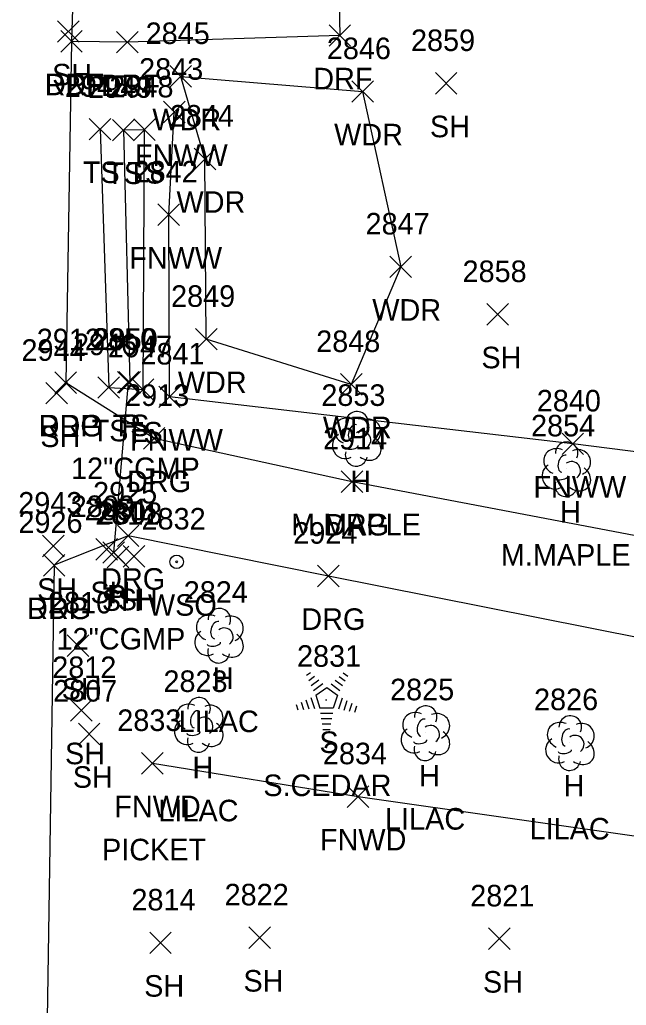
# Model space of a CAD drawing. Extents: x 1609623 to 1616187, y 756677 to 762826.
# Drawn here: x 1610616 to 1610672.3, y 761993.3 to 762084.8 of the extents above; entities that cross this region are included whole.
import ezdxf

# ---------------------------------------------------------------- set-up
doc = ezdxf.new("R2010")
doc.units = 0
for name, color, linetype in [('D_A', 7, 'Continuous'), ('D_C', 7, 'Continuous'), ('D_I', 7, 'Continuous'), ('D_TIC', 7, 'Continuous'), ('DCP', 7, 'Continuous'), ('L_A', 7, 'Continuous'), ('L_C', 7, 'Continuous'), ('L_I', 7, 'Continuous'), ('L_TIC', 7, 'Continuous'), ('LAWA', 7, 'Continuous'), ('LELB', 7, 'Continuous'), ('LFNC', 7, 'Continuous'), ('LTC', 7, 'Continuous'), ('LTD', 7, 'Continuous'), ('P_A', 7, 'Continuous'), ('P_I', 7, 'Continuous'), ('P_TIC', 7, 'Continuous'), ('PET', 7, 'Continuous'), ('R_A', 7, 'Continuous'), ('R_I', 7, 'Continuous'), ('R_TIC', 7, 'Continuous'), ('RDF', 7, 'Continuous'), ('RDG', 7, 'Continuous'), ('U_A', 7, 'Continuous'), ('U_I', 7, 'Continuous'), ('UWV', 7, 'Continuous')]:
    doc.layers.add(name, color=color, linetype=linetype)

msp = doc.modelspace()

# ---------------------------------------------------------------- linework, layer by layer
at = {"layer": 'D_TIC'}
for points in [[(1610625.028, 762050.167), (1610627.028, 762052.167)], [(1610627.028, 762050.167), (1610625.028, 762052.167)], [(1610623.685, 762034.355), (1610625.685, 762036.355)], [(1610625.685, 762034.355), (1610623.685, 762036.355)]]:
    msp.add_lwpolyline(points, dxfattribs=at)
at = {"layer": 'DCP'}
msp.add_lwpolyline([(1610626.028, 762051.167), (1610624.685, 762035.355)], dxfattribs=at)
at = {"layer": 'L_TIC'}
for points in [[(1610619.487, 762082.696), (1610621.487, 762084.696)], [(1610621.487, 762082.696), (1610619.487, 762084.696)], [(1610629.913, 762078.538), (1610631.913, 762080.538)], [(1610631.913, 762078.538), (1610629.913, 762080.538)], [(1610654.549, 762077.888), (1610656.549, 762079.888)], [(1610656.549, 762077.888), (1610654.549, 762079.888)], [(1610646.786, 762077.134), (1610648.786, 762079.134)], [(1610648.786, 762077.134), (1610646.786, 762079.134)], [(1610629.31, 762075.224), (1610631.31, 762077.224)], [(1610631.31, 762075.224), (1610629.31, 762077.224)], [(1610622.417, 762073.638), (1610624.417, 762075.638)], [(1610624.417, 762073.638), (1610622.417, 762075.638)], [(1610624.586, 762073.545), (1610626.586, 762075.545)], [(1610626.586, 762073.545), (1610624.586, 762075.545)], [(1610626.549, 762073.587), (1610628.549, 762075.587)], [(1610628.549, 762073.587), (1610626.549, 762075.587)], [(1610632.154, 762070.879), (1610634.154, 762072.879)], [(1610634.154, 762070.879), (1610632.154, 762072.879)], [(1610628.792, 762065.698), (1610630.792, 762067.698)], [(1610630.792, 762065.698), (1610628.792, 762067.698)], [(1610650.324, 762060.865), (1610652.324, 762062.865)], [(1610652.324, 762060.865), (1610650.324, 762062.865)], [(1610659.325, 762056.449), (1610661.325, 762058.449)], [(1610661.325, 762056.449), (1610659.325, 762058.449)], [(1610632.28, 762054.151), (1610634.28, 762056.151)], [(1610634.28, 762054.151), (1610632.28, 762056.151)], [(1610625.173, 762050.15), (1610627.173, 762052.15)], [(1610627.173, 762050.15), (1610625.173, 762052.15)], [(1610623.227, 762049.668), (1610625.227, 762051.668)], [(1610625.227, 762049.668), (1610623.227, 762051.668)], [(1610626.411, 762049.471), (1610628.411, 762051.471)], [(1610628.411, 762049.471), (1610626.411, 762051.471)], [(1610645.741, 762049.958), (1610647.741, 762051.958)], [(1610647.741, 762049.958), (1610645.741, 762051.958)], [(1610618.39, 762049.14), (1610620.39, 762051.14)], [(1610620.39, 762049.14), (1610618.39, 762051.14)], [(1610628.863, 762048.802), (1610630.863, 762050.802)], [(1610630.863, 762048.802), (1610628.863, 762050.802)], [(1610666.301, 762044.445), (1610668.301, 762046.445)], [(1610668.301, 762044.445), (1610666.301, 762046.445)], [(1610618.09, 762034.964), (1610620.09, 762036.964)], [(1610620.09, 762034.964), (1610618.09, 762036.964)], [(1610623.041, 762034.648), (1610625.041, 762036.648)], [(1610625.041, 762034.648), (1610623.041, 762036.648)], [(1610624.097, 762033.94), (1610626.097, 762035.94)], [(1610626.097, 762033.94), (1610624.097, 762035.94)], [(1610625.576, 762033.997), (1610627.576, 762035.997)], [(1610627.576, 762033.997), (1610625.576, 762035.997)], [(1610620.371, 762025.706), (1610622.371, 762027.706)], [(1610622.371, 762025.706), (1610620.371, 762027.706)], [(1610620.678, 762019.708), (1610622.678, 762021.708)], [(1610622.678, 762019.708), (1610620.678, 762021.708)], [(1610621.406, 762017.523), (1610623.406, 762019.523)], [(1610623.406, 762017.523), (1610621.406, 762019.523)], [(1610627.279, 762014.794), (1610629.279, 762016.794)], [(1610629.279, 762014.794), (1610627.279, 762016.794)], [(1610646.364, 762011.709), (1610648.364, 762013.709)], [(1610648.364, 762011.709), (1610646.364, 762013.709)], [(1610628.028, 761998.14), (1610630.028, 762000.14)], [(1610630.028, 761998.14), (1610628.028, 762000.14)], [(1610637.242, 761998.612), (1610639.242, 762000.612)], [(1610639.242, 761998.612), (1610637.242, 762000.612)], [(1610659.471, 761998.517), (1610661.471, 762000.517)], [(1610661.471, 761998.517), (1610659.471, 762000.517)]]:
    msp.add_lwpolyline(points, dxfattribs=at)
at = {"layer": 'LAWA'}
for points in [[(1610633.154, 762071.879), (1610630.913, 762079.538), (1610647.786, 762078.134), (1610651.324, 762061.865), (1610646.741, 762050.958), (1610633.28, 762055.151)], [(1610633.28, 762055.151), (1610633.154, 762071.879)]]:
    msp.add_lwpolyline(points, dxfattribs=at)
at = {"layer": 'LELB'}
msp.add_lwpolyline([(1610623.417, 762074.638), (1610624.227, 762050.668), (1610627.411, 762050.471), (1610627.549, 762074.587), (1610625.586, 762074.545), (1610626.173, 762051.15)], dxfattribs=at)
at = {"layer": 'LFNC'}
for points in [[(1610758.962, 762033.074), (1610692.81, 762042.187), (1610667.301, 762045.445), (1610629.863, 762049.802), (1610629.792, 762066.698), (1610630.31, 762076.224)], [(1610628.279, 762015.794), (1610647.364, 762012.709), (1610689.696, 762006.674)]]:
    msp.add_lwpolyline(points, dxfattribs=at)
at = {"layer": 'LTC'}
for p, q in [((1610642.59, 762023.96), (1610642.945, 762024.217)), ((1610642.8, 762023.494), (1610643.329, 762023.878)), ((1610645.617, 762023.852), (1610646.167, 762023.453)), ((1610645.988, 762024.2), (1610646.408, 762023.896)), ((1610643.009, 762023.028), (1610643.713, 762023.54)), ((1610643.219, 762022.563), (1610644.097, 762023.201)), ((1610643.443, 762022.108), (1610644.455, 762022.842)), ((1610644.455, 762022.842), (1610645.452, 762022.117)), ((1610644.875, 762023.155), (1610645.685, 762022.566)), ((1610645.246, 762023.503), (1610645.925, 762023.01)), ((1610643.443, 762022.108), (1610643.83, 762020.914)), ((1610645.452, 762022.117), (1610645.061, 762020.914)), ((1610641.623, 762021.239), (1610641.775, 762020.771)), ((1610642.078, 762021.456), (1610642.29, 762020.804)), ((1610642.533, 762021.672), (1610642.805, 762020.837)), ((1610642.989, 762021.888), (1610643.32, 762020.869)), ((1610645.89, 762021.846), (1610645.552, 762020.807)), ((1610646.334, 762021.596), (1610646.047, 762020.711)), ((1610646.779, 762021.346), (1610646.542, 762020.616)), ((1610647.223, 762021.096), (1610647.036, 762020.521)), ((1610645.061, 762020.914), (1610643.83, 762020.914)), ((1610645.023, 762020.414), (1610643.878, 762020.414)), ((1610644.939, 762019.914), (1610643.95, 762019.914)), ((1610644.855, 762019.414), (1610644.023, 762019.414)), ((1610644.771, 762018.914), (1610644.096, 762018.914))]:
    msp.add_line(p, q, dxfattribs=at)
at = {"layer": 'LTD'}
for p, q in [((1610647.22, 762045.958), (1610647.22, 762045.958)), ((1610647.22, 762045.958), (1610647.22, 762045.958)), ((1610666.683, 762043.131), (1610666.683, 762043.131)), ((1610666.683, 762043.131), (1610666.683, 762043.131)), ((1610634.446, 762027.69), (1610634.446, 762027.69)), ((1610634.446, 762027.69), (1610634.446, 762027.69)), ((1610632.564, 762019.413), (1610632.564, 762019.413)), ((1610632.564, 762019.413), (1610632.564, 762019.413)), ((1610653.598, 762018.644), (1610653.598, 762018.644)), ((1610653.598, 762018.644), (1610653.598, 762018.644)), ((1610667.016, 762017.726), (1610667.016, 762017.726)), ((1610667.016, 762017.726), (1610667.016, 762017.726))]:
    msp.add_line(p, q, dxfattribs=at)
for centre in [(1610647.267, 762047.392), (1610666.729, 762044.565), (1610634.493, 762029.123), (1610632.611, 762020.847), (1610653.645, 762020.078), (1610667.062, 762019.16)]:
    msp.add_arc(centre, 1.047, 335.52715, 180.95627, dxfattribs=at)
for centre, major_axis, ratio, start_param, end_param in [((1610646.428, 762046.624), (1.21, -0.512), 0.895232, 1.570796, 4.712389), ((1610648.262, 762046.541), (-1.141, -0.483), 0.949671, 1.570796, 4.712389), ((1610647.012, 762046.416), (-0.208, -0.792), 0.645439, 3.141593, 6.283185), ((1610647.72, 762045.791), (-0.5, 0.667), 0.989748, 3.141593, 6.283185), ((1610646.137, 762045.249), (0.584, -1.042), 0.959034, 3.141593, 6.283185), ((1610648.22, 762045.125), (-1.09, 0.792), 0.841452, 1.570796, 4.712389), ((1610646.762, 762045.208), (-0.625, -0.083), 0.423636, 0, 3.141593), ((1610665.891, 762043.797), (1.21, -0.512), 0.895232, 1.570796, 4.712389), ((1610667.724, 762043.714), (-1.141, -0.483), 0.949671, 1.570796, 4.712389), ((1610647.22, 762044.458), (0.265, 1.061), 0.942809, 1.570796, 4.712389), ((1610666.474, 762043.589), (-0.208, -0.792), 0.645439, 3.141593, 6.283185), ((1610667.183, 762042.964), (-0.5, 0.667), 0.989748, 3.141593, 6.283185), ((1610665.599, 762042.422), (0.584, -1.042), 0.959034, 3.141593, 6.283185), ((1610667.683, 762042.298), (-1.09, 0.792), 0.841452, 1.570796, 4.712389), ((1610666.224, 762042.381), (-0.625, -0.083), 0.423636, 0, 3.141593), ((1610666.683, 762041.631), (0.265, 1.061), 0.942809, 1.570796, 4.712389), ((1610633.654, 762028.356), (1.21, -0.512), 0.895232, 1.570796, 4.712389), ((1610635.488, 762028.273), (-1.141, -0.483), 0.949671, 1.570796, 4.712389), ((1610634.238, 762028.148), (-0.208, -0.792), 0.645439, 3.141593, 6.283185), ((1610634.946, 762027.523), (-0.5, 0.667), 0.989748, 3.141593, 6.283185), ((1610633.363, 762026.981), (0.584, -1.042), 0.959034, 3.141593, 6.283185), ((1610635.446, 762026.856), (-1.09, 0.792), 0.841452, 1.570796, 4.712389), ((1610633.988, 762026.939), (-0.625, -0.083), 0.423636, 0, 3.141593), ((1610634.446, 762026.19), (0.265, 1.061), 0.942809, 1.570796, 4.712389), ((1610631.773, 762020.079), (1.21, -0.512), 0.895232, 1.570796, 4.712389), ((1610633.606, 762019.996), (-1.141, -0.483), 0.949671, 1.570796, 4.712389), ((1610632.356, 762019.871), (-0.208, -0.792), 0.645439, 3.141593, 6.283185), ((1610633.065, 762019.246), (-0.5, 0.667), 0.989748, 3.141593, 6.283185), ((1610652.806, 762019.31), (1.21, -0.512), 0.895232, 1.570796, 4.712389), ((1610654.64, 762019.227), (-1.141, -0.483), 0.949671, 1.570796, 4.712389), ((1610631.481, 762018.704), (0.584, -1.042), 0.959034, 3.141593, 6.283185), ((1610633.565, 762018.579), (-1.09, 0.792), 0.841452, 1.570796, 4.712389), ((1610653.39, 762019.102), (-0.208, -0.792), 0.645439, 3.141593, 6.283185), ((1610654.098, 762018.477), (-0.5, 0.667), 0.989748, 3.141593, 6.283185), ((1610666.224, 762018.392), (1.21, -0.512), 0.895232, 1.570796, 4.712389), ((1610668.057, 762018.309), (-1.141, -0.483), 0.949671, 1.570796, 4.712389), ((1610632.106, 762018.663), (-0.625, -0.083), 0.423636, 0, 3.141593), ((1610652.515, 762017.935), (0.584, -1.042), 0.959034, 3.141593, 6.283185), ((1610654.598, 762017.811), (-1.09, 0.792), 0.841452, 1.570796, 4.712389), ((1610666.807, 762018.184), (-0.208, -0.792), 0.645439, 3.141593, 6.283185), ((1610667.516, 762017.559), (-0.5, 0.667), 0.989748, 3.141593, 6.283185), ((1610632.565, 762017.913), (0.265, 1.061), 0.942809, 1.570796, 4.712389), ((1610653.599, 762017.144), (0.265, 1.061), 0.942809, 1.570796, 4.712389), ((1610653.14, 762017.894), (-0.625, -0.083), 0.423636, 0, 3.141593), ((1610665.932, 762017.017), (0.584, -1.042), 0.959034, 3.141593, 6.283185), ((1610668.016, 762016.893), (-1.09, 0.792), 0.841452, 1.570796, 4.712389), ((1610667.016, 762016.226), (0.265, 1.061), 0.942809, 1.570796, 4.712389), ((1610666.557, 762016.976), (-0.625, -0.083), 0.423636, 0, 3.141593)]:
    msp.add_ellipse(centre, major_axis=major_axis, ratio=ratio, start_param=start_param, end_param=end_param, dxfattribs=at)
at = {"layer": 'P_TIC'}
for points in [[(1610619.776, 762081.781), (1610621.776, 762083.781)], [(1610621.776, 762081.781), (1610619.776, 762083.781)], [(1610619.24, 762050.122), (1610621.24, 762052.122)], [(1610621.24, 762050.122), (1610619.24, 762052.122)], [(1610618.159, 762033.171), (1610620.159, 762035.171)], [(1610620.159, 762033.171), (1610618.159, 762035.171)]]:
    msp.add_lwpolyline(points, dxfattribs=at)
at = {"layer": 'PET'}
for points in [[(1610622.044, 762167.749), (1610622.434, 762137.471), (1610620.776, 762082.781), (1610620.24, 762051.122)], [(1610619.159, 762034.171), (1610618.457, 761988.073), (1610618.105, 761954.066), (1610618.601, 761923.518), (1610618.231, 761918.549), (1610617.677, 761897.504)]]:
    msp.add_lwpolyline(points, dxfattribs=at)
at = {"layer": 'R_TIC'}
for points in [[(1610644.675, 762082.332), (1610646.675, 762084.332)], [(1610646.675, 762082.332), (1610644.675, 762084.332)], [(1610619.776, 762081.781), (1610621.776, 762083.781)], [(1610621.776, 762081.781), (1610619.776, 762083.781)], [(1610624.962, 762081.709), (1610626.962, 762083.709)], [(1610626.962, 762081.709), (1610624.962, 762083.709)], [(1610619.24, 762050.122), (1610621.24, 762052.122)], [(1610621.24, 762050.122), (1610619.24, 762052.122)], [(1610627.441, 762044.957), (1610629.441, 762046.957)], [(1610629.441, 762044.957), (1610627.441, 762046.957)], [(1610645.813, 762040.93), (1610647.813, 762042.93)], [(1610647.813, 762040.93), (1610645.813, 762042.93)], [(1610625.033, 762035.902), (1610627.033, 762037.902)], [(1610627.033, 762035.902), (1610625.033, 762037.902)], [(1610618.159, 762033.171), (1610620.159, 762035.171)], [(1610620.159, 762033.171), (1610618.159, 762035.171)], [(1610643.616, 762032.174), (1610645.616, 762034.174)], [(1610645.616, 762032.174), (1610643.616, 762034.174)]]:
    msp.add_lwpolyline(points, dxfattribs=at)
at = {"layer": 'RDF'}
msp.add_lwpolyline([(1610622.434, 762137.471), (1610621.579, 762091.958), (1610625.526, 762092.036), (1610645.506, 762090.888), (1610645.675, 762083.332), (1610625.962, 762082.709), (1610620.776, 762082.781)], dxfattribs=at)
at = {"layer": 'RDG'}
for points in [[(1610620.24, 762051.122), (1610628.441, 762045.957), (1610646.813, 762041.93), (1610677.554, 762036.092), (1610695.287, 762033.44)], [(1610729.298, 762004.607), (1610720.679, 762005.774), (1610712.97, 762015.55), (1610702.281, 762020.369), (1610678.719, 762026.383), (1610644.616, 762033.174), (1610626.033, 762036.902), (1610619.159, 762034.171)]]:
    msp.add_lwpolyline(points, dxfattribs=at)
at = {"layer": 'UWV'}
for radius in [0.625, 0.0833]:
    msp.add_circle((1610630.535, 762034.488), radius, dxfattribs=at)

# ---------------------------------------------------------------- texts
at = {"layer": 'D_A'}
for p in [(1610625.406, 762046.167), (1610624.063, 762030.355)]:
    msp.add_text('P', height=2, dxfattribs=at).set_placement(p)
at = {"layer": 'D_C'}
for p in [(1610620.729, 762042.167), (1610619.386, 762026.355)]:
    msp.add_text('12"CGMP', height=2, dxfattribs=at).set_placement(p)
at = {"layer": 'D_I'}
for s, p in [('2850', (1610622.682, 762054.167)), ('2851', (1610621.992, 762038.355))]:
    msp.add_text(s, height=2, dxfattribs=at).set_placement(p)
at = {"layer": 'L_A'}
for s, p in [('SH', (1610618.975, 762078.696)), ('WDR', (1610628.275, 762074.538)), ('SH', (1610654.037, 762073.888)), ('WDR', (1610645.148, 762073.134)), ('FNWW', (1610626.657, 762071.224)), ('TS', (1610621.826, 762069.638)), ('TS', (1610623.995, 762069.545)), ('TS', (1610625.959, 762069.587)), ('WDR', (1610630.516, 762066.879)), ('FNWW', (1610626.138, 762061.698)), ('WDR', (1610648.686, 762056.865)), ('SH', (1610658.813, 762052.449)), ('WDR', (1610630.642, 762050.151)), ('TS', (1610622.636, 762045.668)), ('TS', (1610624.583, 762046.15)), ('TS', (1610625.821, 762045.471)), ('WDR', (1610644.104, 762045.958)), ('SH', (1610617.878, 762045.14)), ('FNWW', (1610626.209, 762044.802)), ('H', (1610646.653, 762040.958)), ('FNWW', (1610663.647, 762040.445)), ('H', (1610666.116, 762038.131)), ('SH', (1610617.578, 762030.964)), ('SH', (1610622.529, 762030.648)), ('SH', (1610623.585, 762029.94)), ('SH', (1610625.064, 762029.997)), ('H', (1610633.879, 762022.69)), ('SH', (1610619.859, 762021.706)), ('S', (1610643.781, 762016.752)), ('SH', (1610620.167, 762015.708)), ('H', (1610631.998, 762014.413)), ('SH', (1610620.894, 762013.523)), ('H', (1610653.031, 762013.644)), ('H', (1610666.449, 762012.726)), ('FNWD', (1610624.743, 762010.794)), ('FNWD', (1610643.829, 762007.709)), ('SH', (1610636.73, 761994.612)), ('SH', (1610658.959, 761994.517)), ('SH', (1610627.516, 761994.14))]:
    msp.add_text(s, height=2, dxfattribs=at).set_placement(p)
at = {"layer": 'L_C'}
for s, p in [('M.MAPLE', (1610641.157, 762036.958)), ('M.MAPLE', (1610660.62, 762034.131)), ('LILAC', (1610630.722, 762018.69)), ('S.CEDAR', (1610638.576, 762012.752)), ('LILAC', (1610628.84, 762010.413)), ('LILAC', (1610649.874, 762009.644)), ('LILAC', (1610663.291, 762008.726)), ('PICKET', (1610623.609, 762006.794))]:
    msp.add_text(s, height=2, dxfattribs=at).set_placement(p)
at = {"layer": 'L_I'}
for s, p in [('2845', (1610627.653, 762082.538)), ('2859', (1610652.281, 762081.888)), ('2846', (1610644.471, 762081.134)), ('2843', (1610627.05, 762079.224)), ('2945', (1610620.157, 762077.638)), ('2949', (1610622.318, 762077.545)), ('2948', (1610624.289, 762077.587)), ('2844', (1610629.894, 762074.879)), ('2842', (1610626.532, 762069.698)), ('2847', (1610648.064, 762064.865)), ('2858', (1610657.065, 762060.449)), ('2849', (1610630.012, 762058.151)), ('2950', (1610622.827, 762054.15)), ('2848', (1610643.481, 762053.958)), ('2944', (1610616.13, 762053.14)), ('2946', (1610620.912, 762053.668)), ('2947', (1610624.151, 762053.471)), ('2841', (1610627.17, 762052.802)), ('2853', (1610643.96, 762048.958)), ('2840', (1610663.955, 762048.445)), ('2854', (1610663.423, 762046.131)), ('2943', (1610615.83, 762038.964)), ('2809', (1610620.694, 762038.648)), ('2811', (1610622.971, 762037.94)), ('2808', (1610623.237, 762037.997)), ('2824', (1610631.186, 762030.69)), ('2810', (1610618.591, 762029.706)), ('2831', (1610641.702, 762024.752)), ('2812', (1610618.985, 762023.708)), ('2823', (1610629.305, 762022.413)), ('2807', (1610619.067, 762021.523)), ('2825', (1610650.338, 762021.644)), ('2826', (1610663.701, 762020.726)), ('2833', (1610625.019, 762018.794)), ('2834', (1610644.104, 762015.709)), ('2822', (1610634.982, 762002.612)), ('2821', (1610657.778, 762002.517)), ('2814', (1610626.335, 762002.14))]:
    msp.add_text(s, height=2, dxfattribs=at).set_placement(p)
at = {"layer": 'LTC'}
msp.add_text('.', height=1.037, rotation=270, dxfattribs=at).set_placement((1610644.338, 762021.856))
at = {"layer": 'P_A'}
for p in [(1610618.265, 762077.781), (1610617.728, 762046.122), (1610616.647, 762029.171)]:
    msp.add_text('RDP', height=2, dxfattribs=at).set_placement(p)
at = {"layer": 'P_I'}
for s, p in [('2912', (1610617.547, 762054.122)), ('2926', (1610615.844, 762037.171))]:
    msp.add_text(s, height=2, dxfattribs=at).set_placement(p)
at = {"layer": 'R_A'}
for s, p in [('DRF', (1610618.312, 762077.781)), ('DRF', (1610623.498, 762077.709)), ('DRF', (1610643.21, 762078.332)), ('DRG', (1610617.728, 762046.122)), ('DRG', (1610625.929, 762040.957)), ('DRG', (1610644.302, 762036.93)), ('DRG', (1610623.521, 762031.902)), ('DRG', (1610616.647, 762029.171)), ('DRG', (1610642.104, 762028.174))]:
    msp.add_text(s, height=2, dxfattribs=at).set_placement(p)
at = {"layer": 'R_I'}
for s, p in [('2912', (1610617.547, 762054.122)), ('2913', (1610625.748, 762048.957)), ('2914', (1610644.121, 762044.93)), ('2925', (1610622.773, 762039.902)), ('2926', (1610615.844, 762037.171)), ('2924', (1610641.356, 762036.174))]:
    msp.add_text(s, height=2, dxfattribs=at).set_placement(p)
at = {"layer": 'U_A'}
msp.add_text('WSO', height=2, dxfattribs=at).set_placement((1610627.866, 762029.488))
at = {"layer": 'U_I'}
msp.add_text('2832', height=2, dxfattribs=at).set_placement((1610627.275, 762037.488))

doc.saveas('drawing.dxf')
